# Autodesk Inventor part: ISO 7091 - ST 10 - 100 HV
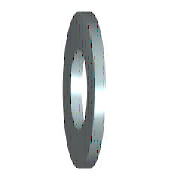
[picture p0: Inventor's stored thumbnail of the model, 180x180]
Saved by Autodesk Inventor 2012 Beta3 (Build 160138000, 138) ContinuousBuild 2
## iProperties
IsCustomPart: 0
Created: 2010-11
Part Number: ISO 7091 - ST 10 - 100 HV
Material: Steel
Description: Plain washers - Normal series - Product grade C
Document SubType Name: Modeling
Standard: ISO 7091
Designer: Beta-8540w
Standard Revision: Second edition 2000-06-01
Standards Organization: ISO
Language: en-US
Size Designation: ST 10 - 100 HV
Categories: <MemberInstance><Categories><Category DisplayName="Fasteners" InternalName="e4da775c-781d-43d5-af7c-5136215cf5a6" Mnemonic="FSTN"><Category DisplayName="Washers
Density: 7.85 g/cm^3
Author: Beta-8540w
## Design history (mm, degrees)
workaxis "Work Axis1"
workplane "Work Plane1"
body "Solid1"
sketch "Sketch"
  geometry: C1 r 10 at (0, 0); C2 r 5.5 at (0, 0); 1 further point
  constraints: 2 centre point, 2 coincident
  dimensions: "d0" = 11 diameter of C2 (= SD1); "d1" = 20 diameter of C1 (= SD2)
extrude "Body" new body sketch "Sketch" distance "d2" = 2 (= SD); taper "d3" = 0 deg
other parameters: "SD1" = 11 [user parameter; used in 1 equation term], "SD2" = 20 [user parameter; used in 1 equation term], "SD" = 2 [user parameter; used in 1 equation term], "d4" = 0, "d5" = 0, "d6" = 0, "d7" = 0
